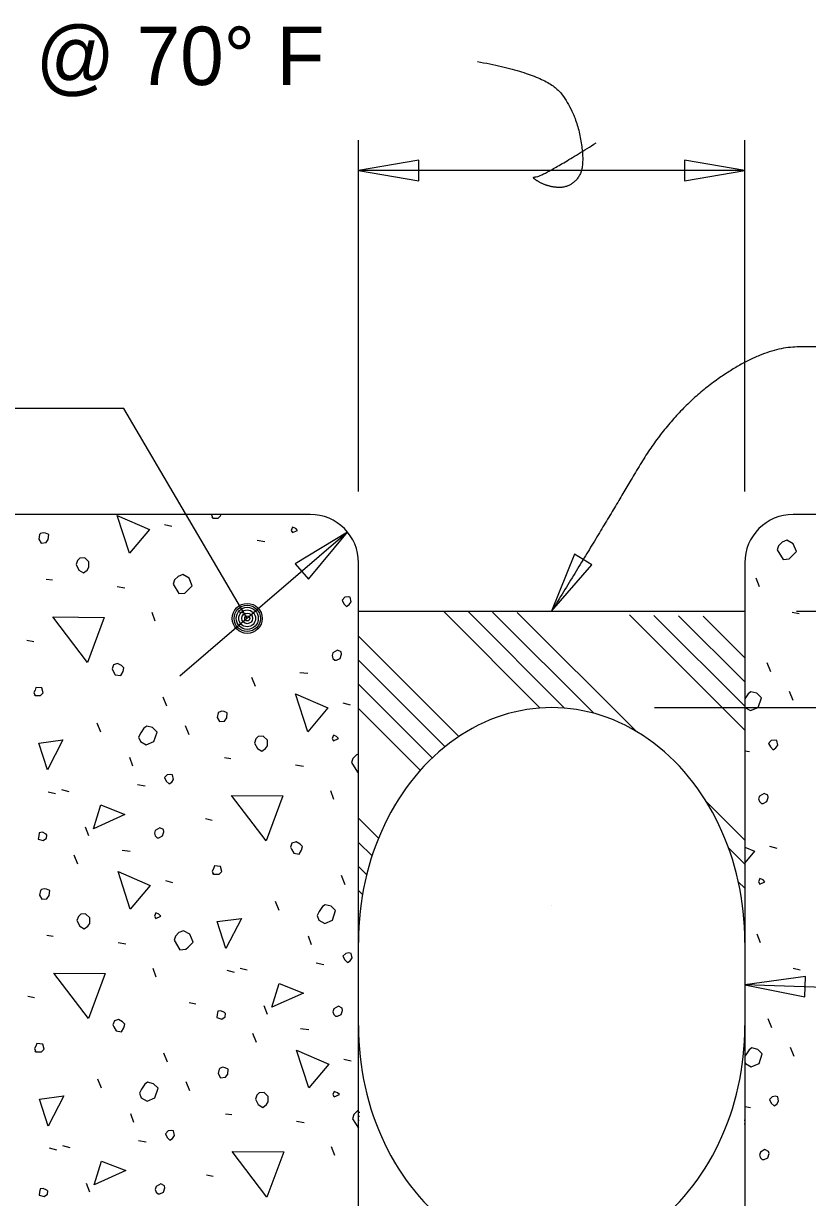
# Model space of a CAD drawing. Extents: x 0 to 15.4, y 0 to 9.7.
# Drawn here: x 3.065 to 4.08, y 3.148 to 4.667 of the extents above; entities that cross this region are included whole.
import ezdxf

# ---------------------------------------------------------------- set-up
doc = ezdxf.new("R2010")
doc.units = 0
for name, color, linetype in [('Dimension', 7, 'Continuous'), ('Miscellaneous', 7, 'Continuous'), ('SupstrConc', 7, 'Continuous'), ('TextStructures', 7, 'Continuous')]:
    doc.layers.add(name, color=color, linetype=linetype)

msp = doc.modelspace()

# ---------------------------------------------------------------- linework, layer by layer
at = {"layer": 'Dimension'}
for p, q in [((3.4987, 4.0618), (3.4987, 4.5165)), ((3.9984, 4.0618), (3.9984, 4.5165)), ((3.9984, 4.4772), (3.4987, 4.4772)), ((3.4845, 4.0093), (3.2676, 3.8228)), ((4.0652, 3.9072), (6.0609, 3.9072)), ((3.8815, 3.7822), (6.0609, 3.7822)), ((3.4987, 3.3707), (3.4987, 3.4785)), ((3.9984, 3.4785), (3.9984, 3.3707)), ((5.5362, 3.3743), (3.9985, 3.4235))]:
    msp.add_line(p, q, dxfattribs=at)
for points in [[(3.4987, 4.4772), (3.5768, 4.464), (3.5768, 4.4904)], [(3.9984, 4.4772), (3.9203, 4.4904), (3.9203, 4.464)], [(3.4845, 4.0093), (3.4167, 3.9684), (3.4339, 3.9484)], [(3.7485, 3.9072), (3.8007, 3.9668), (3.7782, 3.9806)], [(3.9984, 3.4235), (4.0761, 3.4078), (4.0769, 3.4342)]]:
    msp.add_lwpolyline(points, close=True, dxfattribs=at)
msp.add_lwpolyline([(3.3546, 3.8976), (3.1952, 4.1694), (3.044, 4.1694)], dxfattribs=at)
for radius in [0.0194, 0.017, 0.0143, 0.0109, 0.00692, 0.00329]:
    msp.add_circle((3.3547, 3.8977), radius, dxfattribs=at)
for centre, start_param, end_param in [((3.7486, 3.4785), 4.712389, 7.853982), ((3.7486, 3.3707), 1.570796, 4.712389)]:
    msp.add_ellipse(centre, major_axis=(0, 0.3037), ratio=0.822917, start_param=start_param, end_param=end_param, dxfattribs=at)
for points in [[(3.6526, 4.6183), (3.7408, 4.6022), (3.7799, 4.5529), (3.7926, 4.4808), (3.7731, 4.4553), (3.7451, 4.4553), (3.7205, 4.4689), (3.7357, 4.4689), (3.8062, 4.513)], [(4.1737, 4.2489), (4.113, 4.2489), (4.0218, 4.2489), (3.9022, 4.1634), (3.8186, 4.021), (3.7486, 3.9072)]]:
    msp.add_open_spline(points, degree=2, dxfattribs=at)
at = {"layer": 'Miscellaneous'}
for p, q in [((3.2476, 4.0192), (3.257, 4.0169)), ((3.3676, 3.999), (3.3776, 3.9972)), ((4.0175, 3.9387), (4.0134, 3.9499)), ((3.0944, 3.9485), (3.1026, 3.9474)), ((3.1863, 3.9391), (3.1963, 3.9373)), ((3.2358, 3.8943), (3.2317, 3.9055)), ((3.3442, 3.9061), (3.3536, 3.9038)), ((3.4987, 3.9072), (3.9984, 3.9072)), ((3.6085, 3.9071), (3.7339, 3.7817)), ((3.6404, 3.9065), (3.7653, 3.7815)), ((3.6722, 3.9058), (3.8032, 3.7749)), ((3.704, 3.9052), (3.8573, 3.752)), ((4.0599, 3.9057), (4.0688, 3.9039)), ((3.8491, 3.9023), (3.9984, 3.753)), ((3.881, 3.9016), (3.9984, 3.7842)), ((3.9128, 3.901), (3.9984, 3.8154)), ((3.9446, 3.9004), (3.9984, 3.8466)), ((3.4987, 3.8748), (3.6286, 3.7449)), ((3.0696, 3.8696), (3.0785, 3.8678)), ((3.4987, 3.8436), (3.6106, 3.7317)), ((4.0322, 3.8285), (4.0275, 3.8403)), ((3.3654, 3.8095), (3.3607, 3.8213)), ((3.4226, 3.8277), (3.4332, 3.8266)), ((3.4987, 3.8124), (3.5939, 3.7171)), ((4.0611, 3.7914), (4.0564, 3.8032)), ((3.2505, 3.7841), (3.2458, 3.7959)), ((3.4786, 3.7883), (3.488, 3.7859)), ((3.4987, 3.7812), (3.5786, 3.7012)), ((3.1651, 3.7505), (3.1604, 3.7623)), ((3.2794, 3.747), (3.2747, 3.7588)), ((3.9984, 3.7265), (4.0046, 3.7254)), ((3.2069, 3.7064), (3.2028, 3.7175)), ((3.3254, 3.7175), (3.3336, 3.7164)), ((3.4173, 3.7081), (3.4273, 3.7064)), ((3.2128, 3.6828), (3.2228, 3.681)), ((3.0973, 3.6734), (3.1068, 3.671)), ((3.1144, 3.6763), (3.1238, 3.6739)), ((3.4668, 3.6633), (3.4627, 3.6745)), ((3.9484, 3.6608), (3.9984, 3.6109)), ((3.3006, 3.6386), (3.3095, 3.6368)), ((3.4987, 3.639), (3.5245, 3.6131)), ((3.1498, 3.6162), (3.1456, 3.6274)), ((3.4987, 3.6078), (3.5162, 3.5903)), ((3.9773, 3.6007), (3.9984, 3.5797)), ((4.0305, 3.6028), (4.0399, 3.6005)), ((3.1356, 3.5797), (3.1309, 3.5914)), ((3.1928, 3.5979), (3.2034, 3.5967)), ((3.4987, 3.5766), (3.5093, 3.566)), ((3.2488, 3.5584), (3.2582, 3.5561)), ((3.4815, 3.5531), (3.4768, 3.5649)), ((3.99, 3.5568), (3.9984, 3.5485)), ((3.4987, 3.5454), (3.5039, 3.5402)), ((3.3961, 3.5196), (3.3914, 3.5313)), ((3.7484, 3.5259), (3.7484, 3.5259)), ((3.0956, 3.4877), (3.1038, 3.4866)), ((3.4379, 3.4754), (3.4338, 3.4866)), ((4.0187, 3.4779), (4.0146, 3.4891)), ((3.1875, 3.4783), (3.1975, 3.4765)), ((3.4438, 3.4518), (3.4538, 3.45)), ((3.237, 3.4335), (3.2329, 3.4447)), ((3.3283, 3.4424), (3.3377, 3.44)), ((3.3454, 3.4453), (3.3548, 3.443)), ((4.0611, 3.4449), (4.07, 3.4431)), ((3.0708, 3.4088), (3.0796, 3.407)), ((3.2794, 3.4005), (3.2882, 3.3988)), ((3.3808, 3.3852), (3.3766, 3.3964)), ((4.0334, 3.3677), (4.0287, 3.3795)), ((3.3666, 3.3487), (3.3619, 3.3605)), ((3.4238, 3.3669), (3.4344, 3.3658)), ((4.0623, 3.3306), (4.0576, 3.3424)), ((3.2517, 3.3233), (3.247, 3.3351)), ((3.4798, 3.3275), (3.4892, 3.3251)), ((3.1663, 3.2897), (3.1616, 3.3015)), ((3.2806, 3.2862), (3.2759, 3.298)), ((3.2081, 3.2456), (3.204, 3.2567)), ((3.3265, 3.2567), (3.3348, 3.2556)), ((3.4987, 3.2586), (3.5005, 3.2586)), ((3.4987, 3.2536), (3.5, 3.2536)), ((3.9984, 3.2659), (4.0057, 3.2646)), ((3.4185, 3.2473), (3.4285, 3.2456)), ((3.4987, 3.2486), (3.4996, 3.2486)), ((3.4987, 3.2436), (3.4993, 3.2436)), ((3.4987, 3.2386), (3.4991, 3.2386)), ((3.9975, 3.2486), (3.9984, 3.2486)), ((3.9978, 3.2436), (3.9984, 3.2436)), ((3.998, 3.2386), (3.9984, 3.2386)), ((3.214, 3.222), (3.224, 3.2202)), ((3.4987, 3.2336), (3.4988, 3.2336)), ((3.4987, 3.2286), (3.4988, 3.2286)), ((3.4987, 3.2236), (3.4987, 3.2236)), ((3.9982, 3.2336), (3.9984, 3.2336)), ((3.9984, 3.2286), (3.9984, 3.2286)), ((3.9984, 3.2236), (3.9984, 3.2236)), ((3.0985, 3.2126), (3.1079, 3.2102)), ((3.1156, 3.2155), (3.125, 3.2131)), ((3.468, 3.2025), (3.4638, 3.2137)), ((3.3018, 3.1778), (3.3106, 3.176)), ((3.1509, 3.1554), (3.1468, 3.1666))]:
    msp.add_line(p, q, dxfattribs=at)
for points in [[(3.2022, 3.9821), (3.1863, 4.031), (3.2281, 4.0128), (3.2022, 3.9821)], [(3.3086, 4.0322), (3.3083, 4.0316), (3.31, 4.0275), (3.3089, 4.0287)], [(3.31, 4.0275), (3.3171, 4.0275), (3.3207, 4.031), (3.3203, 4.0322)], [(3.4133, 4.0087), (3.4198, 4.0116), (3.4174, 4.014), (3.4133, 4.0158), (3.4115, 4.0116), (3.4133, 4.0087)], [(3.0849, 4.0004), (3.0879, 3.9951), (3.0944, 3.9957), (3.0973, 3.9998), (3.0979, 4.0063), (3.0938, 4.008), (3.0908, 4.0086), (3.0873, 4.0075), (3.0861, 4.0063), (3.0849, 4.0004)], [(4.0405, 3.9864), (4.0482, 3.9741), (4.0558, 3.9746), (4.0588, 3.9776), (4.0652, 3.9841), (4.0611, 3.9941), (4.0529, 3.9988), (4.047, 3.9964), (4.0423, 3.9917), (4.0405, 3.9864)], [(3.1333, 3.9674), (3.1368, 3.9603), (3.1427, 3.9568), (3.1474, 3.9603), (3.1498, 3.9639), (3.1498, 3.9709), (3.1445, 3.9762), (3.138, 3.9756), (3.135, 3.9727), (3.1333, 3.9674)], [(3.2588, 3.9421), (3.2664, 3.9297), (3.2741, 3.9303), (3.277, 3.9332), (3.2835, 3.9397), (3.2794, 3.9497), (3.2712, 3.9544), (3.2653, 3.9521), (3.2605, 3.9474), (3.2588, 3.9421)], [(3.4798, 3.9167), (3.4833, 3.9132), (3.4868, 3.9155), (3.4892, 3.9191), (3.488, 3.925), (3.4851, 3.9256), (3.4809, 3.925), (3.4774, 3.9214), (3.4798, 3.9167)], [(3.148, 3.8407), (3.1032, 3.8996), (3.1698, 3.899), (3.148, 3.8407)], [(3.468, 3.8436), (3.4703, 3.8436), (3.475, 3.846), (3.4768, 3.8513), (3.4762, 3.8543), (3.4715, 3.8566), (3.4656, 3.8531), (3.4644, 3.8495), (3.4656, 3.846), (3.468, 3.8436)], [(3.181, 3.8301), (3.1839, 3.8248), (3.191, 3.8236), (3.194, 3.8289), (3.1951, 3.8336), (3.1922, 3.8366), (3.1869, 3.8395), (3.1816, 3.8378), (3.1798, 3.8325), (3.181, 3.8301)], [(3.0802, 3.7977), (3.0873, 3.7977), (3.0908, 3.8012), (3.0891, 3.8077), (3.0814, 3.8083), (3.0802, 3.8048), (3.0785, 3.8018), (3.0802, 3.7977), (3.0791, 3.7989)], [(3.4332, 3.7511), (3.4173, 3.8), (3.4591, 3.7818), (3.4332, 3.7511)], [(3.9984, 3.7824), (4.0057, 3.7784), (4.0158, 3.7825), (4.0199, 3.7949), (4.014, 3.8008), (4.0063, 3.8026), (4.0028, 3.8002), (3.9987, 3.7937), (3.9984, 3.7933)], [(3.3159, 3.7694), (3.3189, 3.7641), (3.3254, 3.7647), (3.3283, 3.7688), (3.3289, 3.7753), (3.3248, 3.7771), (3.3218, 3.7777), (3.3183, 3.7765), (3.3171, 3.7753), (3.3159, 3.7694)], [(3.2164, 3.7382), (3.224, 3.734), (3.234, 3.7382), (3.2382, 3.7505), (3.2323, 3.7564), (3.2246, 3.7582), (3.2211, 3.7558), (3.2169, 3.7494), (3.214, 3.7441), (3.2164, 3.7382)], [(3.0961, 3.7016), (3.0849, 3.7364), (3.1162, 3.7405), (3.0961, 3.7016)], [(3.3643, 3.7364), (3.3678, 3.7293), (3.3737, 3.7258), (3.3784, 3.7293), (3.3808, 3.7329), (3.3808, 3.7399), (3.3755, 3.7452), (3.369, 3.7447), (3.366, 3.7417), (3.3643, 3.7364)], [(3.4662, 3.7393), (3.4727, 3.7423), (3.4703, 3.7447), (3.4662, 3.7464), (3.4644, 3.7423), (3.4662, 3.7393)], [(4.0317, 3.7313), (4.0352, 3.7277), (4.0387, 3.7301), (4.0411, 3.7336), (4.0399, 3.7395), (4.037, 3.7401), (4.0328, 3.7395), (4.0293, 3.736), (4.0317, 3.7313)], [(3.4987, 3.7221), (3.4962, 3.7211), (3.4915, 3.7164), (3.4898, 3.7111)], [(3.4898, 3.7111), (3.4974, 3.6987), (3.4987, 3.6988)], [(3.2499, 3.6869), (3.2535, 3.6834), (3.257, 3.6857), (3.2594, 3.6893), (3.2582, 3.6952), (3.2552, 3.6957), (3.2511, 3.6952), (3.2476, 3.6916), (3.2499, 3.6869)], [(3.379, 3.6097), (3.3342, 3.6686), (3.4008, 3.668), (3.379, 3.6097)], [(4.0199, 3.6582), (4.0222, 3.6582), (4.0269, 3.6606), (4.0287, 3.6659), (4.0281, 3.6688), (4.0234, 3.6712), (4.0175, 3.6676), (4.0163, 3.6641), (4.0175, 3.6606), (4.0199, 3.6582)], [(3.1557, 3.6256), (3.1651, 3.6563), (3.1963, 3.6439), (3.1557, 3.6256)], [(3.0844, 3.6121), (3.0908, 3.6103), (3.095, 3.6132), (3.0956, 3.6174), (3.0944, 3.6186), (3.0897, 3.6209), (3.0855, 3.6203), (3.0849, 3.6162), (3.0844, 3.6121)], [(3.2382, 3.6138), (3.2405, 3.6138), (3.2452, 3.6162), (3.247, 3.6215), (3.2464, 3.6244), (3.2417, 3.6268), (3.2358, 3.6233), (3.2346, 3.6197), (3.2358, 3.6162), (3.2382, 3.6138)], [(3.412, 3.5991), (3.4149, 3.5938), (3.422, 3.5926), (3.4249, 3.5979), (3.4261, 3.6026), (3.4232, 3.6056), (3.4179, 3.6085), (3.4126, 3.6068), (3.4108, 3.6015), (3.412, 3.5991)], [(3.9984, 3.6018), (4.011, 3.5963), (3.9984, 3.5814)], [(3.2034, 3.5213), (3.1875, 3.5702), (3.2293, 3.552), (3.2034, 3.5213)], [(3.3112, 3.5667), (3.3183, 3.5667), (3.3218, 3.5702), (3.3201, 3.5767), (3.3124, 3.5773), (3.3112, 3.5738), (3.3095, 3.5708), (3.3112, 3.5667), (3.31, 3.5679)], [(4.0181, 3.5539), (4.0246, 3.5569), (4.0222, 3.5592), (4.0181, 3.561), (4.0163, 3.5569), (4.0181, 3.5539)], [(3.0861, 3.5396), (3.0891, 3.5343), (3.0956, 3.5349), (3.0985, 3.539), (3.0991, 3.5455), (3.095, 3.5473), (3.092, 3.5478), (3.0885, 3.5467), (3.0873, 3.5455), (3.0861, 3.5396)], [(3.4473, 3.5072), (3.455, 3.5031), (3.465, 3.5072), (3.4691, 3.5196), (3.4633, 3.5254), (3.4556, 3.5272), (3.4521, 3.5249), (3.4479, 3.5184), (3.445, 3.5131), (3.4473, 3.5072)], [(3.1344, 3.5066), (3.138, 3.4995), (3.1439, 3.496), (3.1486, 3.4995), (3.1509, 3.5031), (3.1509, 3.5101), (3.1456, 3.5154), (3.1392, 3.5148), (3.1362, 3.5119), (3.1344, 3.5066)], [(3.2364, 3.5095), (3.2429, 3.5125), (3.2405, 3.5148), (3.2364, 3.5166), (3.2346, 3.5125), (3.2364, 3.5095)], [(3.3271, 3.4706), (3.3159, 3.5054), (3.3472, 3.5095), (3.3271, 3.4706)], [(3.26, 3.4813), (3.2676, 3.4689), (3.2753, 3.4695), (3.2782, 3.4724), (3.2847, 3.4789), (3.2806, 3.4889), (3.2723, 3.4936), (3.2664, 3.4913), (3.2617, 3.4866), (3.26, 3.4813)], [(3.4809, 3.4559), (3.4845, 3.4524), (3.488, 3.4547), (3.4904, 3.4583), (3.4892, 3.4642), (3.4862, 3.4648), (3.4821, 3.4642), (3.4786, 3.4606), (3.4809, 3.4559)], [(3.1492, 3.3799), (3.1044, 3.4388), (3.171, 3.4382), (3.1492, 3.3799)], [(3.3866, 3.3946), (3.3961, 3.4253), (3.4273, 3.4129), (3.3866, 3.3946)], [(3.3153, 3.3811), (3.3218, 3.3793), (3.326, 3.3823), (3.3265, 3.3864), (3.3254, 3.3876), (3.3207, 3.3899), (3.3165, 3.3893), (3.3159, 3.3852), (3.3153, 3.3811)], [(3.4691, 3.3828), (3.4715, 3.3828), (3.4762, 3.3852), (3.478, 3.3905), (3.4774, 3.3935), (3.4727, 3.3958), (3.4668, 3.3923), (3.4656, 3.3887), (3.4668, 3.3852), (3.4691, 3.3828)], [(3.1822, 3.3693), (3.1851, 3.364), (3.1922, 3.3628), (3.1951, 3.3681), (3.1963, 3.3728), (3.1934, 3.3758), (3.1881, 3.3787), (3.1828, 3.377), (3.181, 3.3717), (3.1822, 3.3693)], [(3.0814, 3.3369), (3.0885, 3.3369), (3.092, 3.3404), (3.0903, 3.3469), (3.0826, 3.3475), (3.0814, 3.344), (3.0796, 3.341), (3.0814, 3.3369), (3.0802, 3.3381)], [(3.4344, 3.2903), (3.4185, 3.3392), (3.4603, 3.321), (3.4344, 3.2903)], [(3.9993, 3.3218), (4.0069, 3.3176), (4.0169, 3.3218), (4.0211, 3.3341), (4.0152, 3.34), (4.0075, 3.3418), (4.004, 3.3394), (3.9998, 3.3329), (3.9984, 3.3304)], [(3.3171, 3.3086), (3.3201, 3.3033), (3.3265, 3.3039), (3.3295, 3.308), (3.3301, 3.3145), (3.326, 3.3163), (3.323, 3.3169), (3.3195, 3.3157), (3.3183, 3.3145), (3.3171, 3.3086)], [(3.9984, 3.3238), (3.9993, 3.3218)], [(3.2175, 3.2774), (3.2252, 3.2732), (3.2352, 3.2774), (3.2393, 3.2897), (3.2334, 3.2956), (3.2258, 3.2974), (3.2222, 3.2951), (3.2181, 3.2886), (3.2152, 3.2833), (3.2175, 3.2774)], [(3.3654, 3.2756), (3.369, 3.2685), (3.3749, 3.265), (3.3796, 3.2685), (3.3819, 3.2721), (3.3819, 3.2791), (3.3766, 3.2844), (3.3701, 3.2839), (3.3672, 3.2809), (3.3654, 3.2756)], [(3.4674, 3.2786), (3.4739, 3.2815), (3.4715, 3.2839), (3.4674, 3.2856), (3.4656, 3.2815), (3.4674, 3.2786)], [(3.0973, 3.2408), (3.0861, 3.2756), (3.1174, 3.2797), (3.0973, 3.2408)], [(4.0328, 3.2705), (4.0364, 3.2669), (4.0399, 3.2693), (4.0423, 3.2728), (4.0411, 3.2787), (4.0381, 3.2793), (4.034, 3.2787), (4.0305, 3.2752), (4.0328, 3.2705)], [(3.4987, 3.2608), (3.4974, 3.2603), (3.4927, 3.2556), (3.4909, 3.2503)], [(3.4909, 3.2503), (3.4986, 3.2379), (3.4987, 3.2379)], [(3.2511, 3.2261), (3.2547, 3.2226), (3.2582, 3.2249), (3.2605, 3.2285), (3.2594, 3.2344), (3.2564, 3.2349), (3.2523, 3.2344), (3.2488, 3.2308), (3.2511, 3.2261)], [(3.3802, 3.1489), (3.3354, 3.2078), (3.402, 3.2073), (3.3802, 3.1489)], [(4.0211, 3.1974), (4.0234, 3.1974), (4.0281, 3.1998), (4.0299, 3.2051), (4.0293, 3.208), (4.0246, 3.2104), (4.0187, 3.2068), (4.0175, 3.2033), (4.0187, 3.1998), (4.0211, 3.1974)], [(3.1568, 3.1648), (3.1663, 3.1955), (3.1975, 3.1831), (3.1568, 3.1648)], [(3.0855, 3.1513), (3.092, 3.1495), (3.0961, 3.1525), (3.0967, 3.1566), (3.0956, 3.1578), (3.0908, 3.1601), (3.0867, 3.1595), (3.0861, 3.1554), (3.0855, 3.1513)], [(3.2393, 3.153), (3.2417, 3.153), (3.2464, 3.1554), (3.2482, 3.1607), (3.2476, 3.1636), (3.2429, 3.166), (3.237, 3.1625), (3.2358, 3.1589), (3.237, 3.1554), (3.2393, 3.153)]]:
    msp.add_lwpolyline(points, dxfattribs=at)
at = {"layer": 'SupstrConc'}
for p, q in [((3.4362, 4.0322), (2.0359, 4.0322)), ((5.4409, 4.0322), (4.061, 4.0322)), ((3.4987, 1.9713), (3.4987, 3.9697)), ((3.9985, 3.9697), (3.9985, 1.9713))]:
    msp.add_line(p, q, dxfattribs=at)
for centre, start, end in [((3.4362, 3.9697), 0, 90), ((4.061, 3.9697), 90, 180)]:
    msp.add_arc(centre, 0.0625, start, end, dxfattribs=at)

# ---------------------------------------------------------------- texts
at = {"layer": 'TextStructures'}
msp.add_text('Dim. A @ 70° F', height=0.0756, dxfattribs=at).set_placement((2.7497, 4.5878))

doc.saveas('drawing.dxf')
